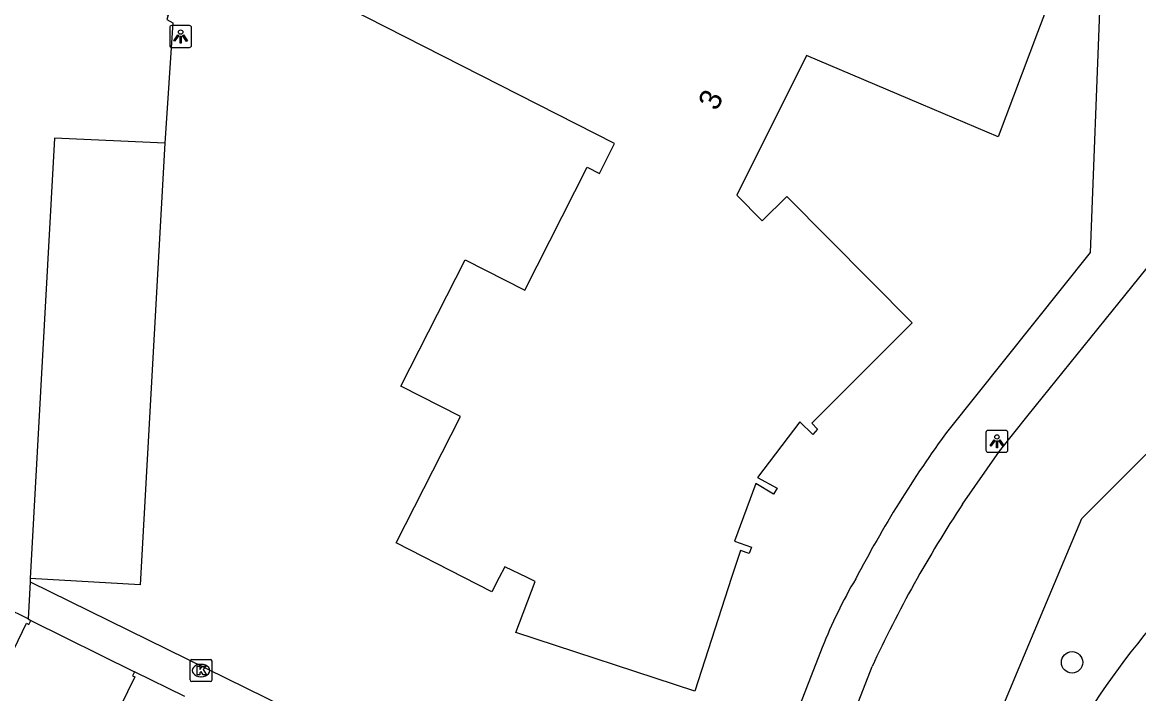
# Model space of a CAD drawing. Extents: x 160356 to 161355, y 381727 to 382845.
# Drawn here: x 160555 to 160606, y 381994.7 to 382025.3 of the extents above; entities that cross this region are included whole.
import ezdxf

# ---------------------------------------------------------------- set-up
doc = ezdxf.new("R2010")
doc.units = 0
for name, color, linetype in [('IMGEO_Boom', 7, 'Continuous'), ('IMGEO_Groenvoorziening', 7, 'Continuous'), ('IMGEO_Hek', 7, 'Continuous'), ('IMGEO_Kolk', 7, 'Continuous'), ('IMGEO_Lichtpunt', 7, 'Continuous'), ('IMGEO_Pand', 7, 'Continuous'), ('IMGEO_Pand_nummerreeks', 7, 'Continuous'), ('IMGEO_Parkeervlak_open', 7, 'Continuous'), ('IMGEO_Rijbaan_lokaal_open', 7, 'Continuous'), ('IMGEO_Voetpad_open', 7, 'Continuous')]:
    doc.layers.add(name, color=color, linetype=linetype)

msp = doc.modelspace()

# ---------------------------------------------------------------- linework, layer by layer
at = {"layer": 'IMGEO_Boom'}
msp.add_circle((160602.927, 381996.132), 0.489, dxfattribs=at)
at = {"layer": 'IMGEO_Groenvoorziening'}
msp.add_lwpolyline([(160595.677, 381984.32), (160600.512, 381995.895), (160603.366, 382002.7), (160611.086, 382010.42), (160614.745, 382009.139), (160618.989, 382008.371), (160622.943, 382011.327)], dxfattribs=at)
at = {"layer": 'IMGEO_Hek'}
msp.add_lwpolyline([(160555.433, 381998.049), (160560.155, 381995.707)], dxfattribs=at)
at = {"layer": 'IMGEO_Kolk'}
for p, q in [((160562.766, 381996.257), (160563.618, 381996.257)), ((160562.691, 381995.331), (160562.691, 381996.183)), ((160563.179, 381996.037), (160563.204, 381996.037)), ((160563.692, 381996.183), (160563.692, 381995.331)), ((160563.618, 381995.257), (160562.766, 381995.257)), ((160563.202, 381995.477), (160563.177, 381995.477))]:
    msp.add_line(p, q, dxfattribs=at)
for points in [[(160562.766, 381996.257), (160563.618, 381996.257)], [(160562.691, 381995.331), (160562.691, 381996.183)], [(160563.012, 381995.957), (160563.135, 381995.957), (160563.135, 381995.806), (160563.265, 381995.957), (160563.429, 381995.957), (160563.283, 381995.806), (160563.436, 381995.557), (160563.284, 381995.557), (160563.199, 381995.721), (160563.135, 381995.654), (160563.135, 381995.557), (160563.012, 381995.557), (160563.012, 381995.957)], [(160563.692, 381996.183), (160563.692, 381995.331)], [(160563.618, 381995.257), (160562.766, 381995.257)]]:
    msp.add_lwpolyline(points, dxfattribs=at)
for centre, start, end in [((160562.768, 381996.181), 91.552, 178.448), ((160562.768, 381996.181), 91.552, 178.448), ((160563.616, 381996.181), 1.552, 88.448), ((160563.616, 381996.181), 1.552, 88.448), ((160562.768, 381995.333), 181.552, 268.448), ((160562.768, 381995.333), 181.552, 268.448), ((160563.616, 381995.333), 271.552, 358.448), ((160563.616, 381995.333), 271.552, 358.448)]:
    msp.add_arc(centre, 0.0765, start, end, dxfattribs=at)
for centre, major_axis, ratio, start_param, end_param in [((160563.178, 381995.757), (-0.387, 0.002), 0.722429, 4.712389, 7.853982), ((160563.203, 381995.757), (-0.39, 0.002), 0.717154, 1.570796, 4.712389)]:
    msp.add_ellipse(centre, major_axis=major_axis, ratio=ratio, start_param=start_param, end_param=end_param, dxfattribs=at)
at = {"layer": 'IMGEO_Lichtpunt'}
for p, q in [((160561.764, 382025.097), (160561.764, 382024.29)), ((160561.764, 382025.097), (160561.764, 382024.29)), ((160562.666, 382025.192), (160561.858, 382025.192)), ((160562.666, 382025.192), (160561.858, 382025.192)), ((160562.76, 382024.29), (160562.76, 382025.097)), ((160562.76, 382024.29), (160562.76, 382025.097)), ((160561.858, 382024.196), (160562.666, 382024.196)), ((160561.858, 382024.196), (160562.666, 382024.196)), ((160599, 382006.622), (160599, 382005.815)), ((160599, 382006.622), (160599, 382005.815)), ((160599.902, 382006.717), (160599.094, 382006.717)), ((160599.902, 382006.717), (160599.094, 382006.717)), ((160599.996, 382005.815), (160599.996, 382006.622)), ((160599.996, 382005.815), (160599.996, 382006.622)), ((160599.094, 382005.721), (160599.902, 382005.721)), ((160599.094, 382005.721), (160599.902, 382005.721))]:
    msp.add_line(p, q, dxfattribs=at)
for points in [[(160562.138, 382024.761), (160562.177, 382024.733), (160561.989, 382024.471), (160561.951, 382024.498), (160562.138, 382024.761)], [(160562.24, 382024.713), (160562.287, 382024.713), (160562.287, 382024.391), (160562.24, 382024.391), (160562.24, 382024.713)], [(160562.35, 382024.733), (160562.388, 382024.76), (160562.575, 382024.498), (160562.536, 382024.47), (160562.35, 382024.733)], [(160599.374, 382006.286), (160599.413, 382006.258), (160599.225, 382005.996), (160599.187, 382006.023), (160599.374, 382006.286)], [(160599.476, 382006.238), (160599.523, 382006.238), (160599.523, 382005.916), (160599.476, 382005.916), (160599.476, 382006.238)], [(160599.586, 382006.258), (160599.624, 382006.285), (160599.811, 382006.023), (160599.772, 382005.995), (160599.586, 382006.258)]]:
    msp.add_lwpolyline(points, dxfattribs=at)
for centre in [(160562.263, 382024.895), (160599.499, 382006.42)]:
    msp.add_circle(centre, 0.0994, dxfattribs=at)
for centre, start, end in [((160561.858, 382025.097), 90, 180), ((160561.858, 382025.097), 90, 180), ((160562.666, 382025.097), 0, 90), ((160562.666, 382025.097), 0, 90), ((160561.858, 382024.29), 180, 270), ((160561.858, 382024.29), 180, 270), ((160562.666, 382024.29), 270, 0), ((160562.666, 382024.29), 270, 360), ((160599.094, 382006.622), 90, 180), ((160599.094, 382006.622), 90, 180), ((160599.902, 382006.622), 0, 90), ((160599.902, 382006.622), 0, 90), ((160599.094, 382005.815), 180, 270), ((160599.094, 382005.815), 180, 270), ((160599.902, 382005.815), 270, 0), ((160599.902, 382005.815), 270, 360)]:
    msp.add_arc(centre, 0.0946, start, end, dxfattribs=at)
at = {"layer": 'IMGEO_Pand'}
for points in [[(160601.909, 382026.364), (160601.348, 382024.877), (160599.551, 382020.118), (160596.039, 382021.61), (160590.819, 382023.827), (160587.632, 382017.457), (160588.796, 382016.283), (160589.91, 382017.389), (160595.637, 382011.618), (160591.061, 382007.043), (160591.321, 382006.766), (160591.1, 382006.532), (160590.512, 382007.1), (160588.582, 382004.564), (160589.479, 382004.075), (160589.314, 382003.805), (160588.496, 382004.296), (160587.535, 382001.665), (160588.306, 382001.384), (160588.2, 382001.093), (160587.802, 382001.24), (160587.398, 382000), (160585.711, 381994.824), (160577.553, 381997.498), (160578.429, 381999.823), (160578.066, 382000), (160577.049, 382000.496), (160576.796, 382000), (160576.462, 381999.347), (160575.185, 382000), (160572.092, 382001.582), (160575.023, 382007.346), (160572.299, 382008.731), (160575.234, 382014.503), (160577.958, 382013.117), (160580.81, 382018.725), (160581.372, 382018.44), (160582.049, 382019.806), (160567.258, 382027.358)], [(160555.302, 381998.113), (160553.189, 381999.15)], [(160551.752, 381996.258), (160553.902, 381995.202), (160555.233, 381997.913), (160555.34, 381997.86), (160555.433, 381998.049)], [(160555.302, 381998.113), (160555.433, 381998.049)], [(160560.155, 381995.707), (160560.065, 381995.522), (160560.173, 381995.47), (160558.843, 381992.758), (160561.008, 381991.699)], [(160562.455, 381994.581), (160560.155, 381995.707)]]:
    msp.add_lwpolyline(points, dxfattribs=at)
at = {"layer": 'IMGEO_Parkeervlak_open'}
msp.add_lwpolyline([(160561.543, 382019.82), (160560.417, 381999.666), (160555.404, 381999.955)], dxfattribs=at)
at = {"layer": 'IMGEO_Rijbaan_lokaal_open'}
for points in [[(160567.62, 382033.798), (160563.756, 382026.216), (160561.616, 382027.336), (160561.005, 382026.029), (160561.7, 382025.66), (160561.631, 382025.459), (160561.904, 382025.308), (160561.543, 382019.82)], [(160561.543, 382019.82), (160556.512, 382020.05), (160555.404, 381999.955)], [(160555.404, 381999.955), (160555.394, 381999.801)], [(160555.394, 381999.801), (160555.302, 381998.113)]]:
    msp.add_lwpolyline(points, dxfattribs=at)
at = {"layer": 'IMGEO_Voetpad_open'}
for points in [[(160604.192, 382026.239), (160603.75, 382014.83), (160597.255, 382006.702)], [(160597.93, 382003.354), (160599.614, 382005.776), (160600.93, 382007.409), (160605.07, 382012.549), (160608.46, 382016.757), (160609.956, 382018.614), (160610.821, 382019.688)], [(160555.394, 381999.801), (160586.709, 381984.411)], [(160555.433, 381998.049), (160560.155, 381995.707)], [(160591.533, 381996.816), (160587.131, 381985.496)], [(160595.677, 381984.32), (160590.164, 381986.55), (160593.801, 381995.937)]]:
    msp.add_lwpolyline(points, dxfattribs=at)
for centre, radius, start, end in [((160640.632, 381975.066), 53.688, 143.8955, 152.3871), ((160627.701, 381979.922), 25.647, 113.1271, 153.6917), ((160645.815, 381971.839), 57.325, 146.6494, 155.14174), ((160633.977, 381974.621), 35.889, 130.7934, 155.1704), ((160612.091, 381988.744), 22.086, 149.5116, 158.5639)]:
    msp.add_arc(centre, radius, start, end, dxfattribs=at)

# ---------------------------------------------------------------- texts
at = {"layer": 'IMGEO_Pand_nummerreeks'}
msp.add_text('3', height=1, rotation=63.4207, dxfattribs=at).set_placement((160586.715, 382021.257))

doc.saveas('drawing.dxf')
